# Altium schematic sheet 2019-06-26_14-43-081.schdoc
size 394 x 127 mm; SheetNumber: 1; SheetTotal: 1
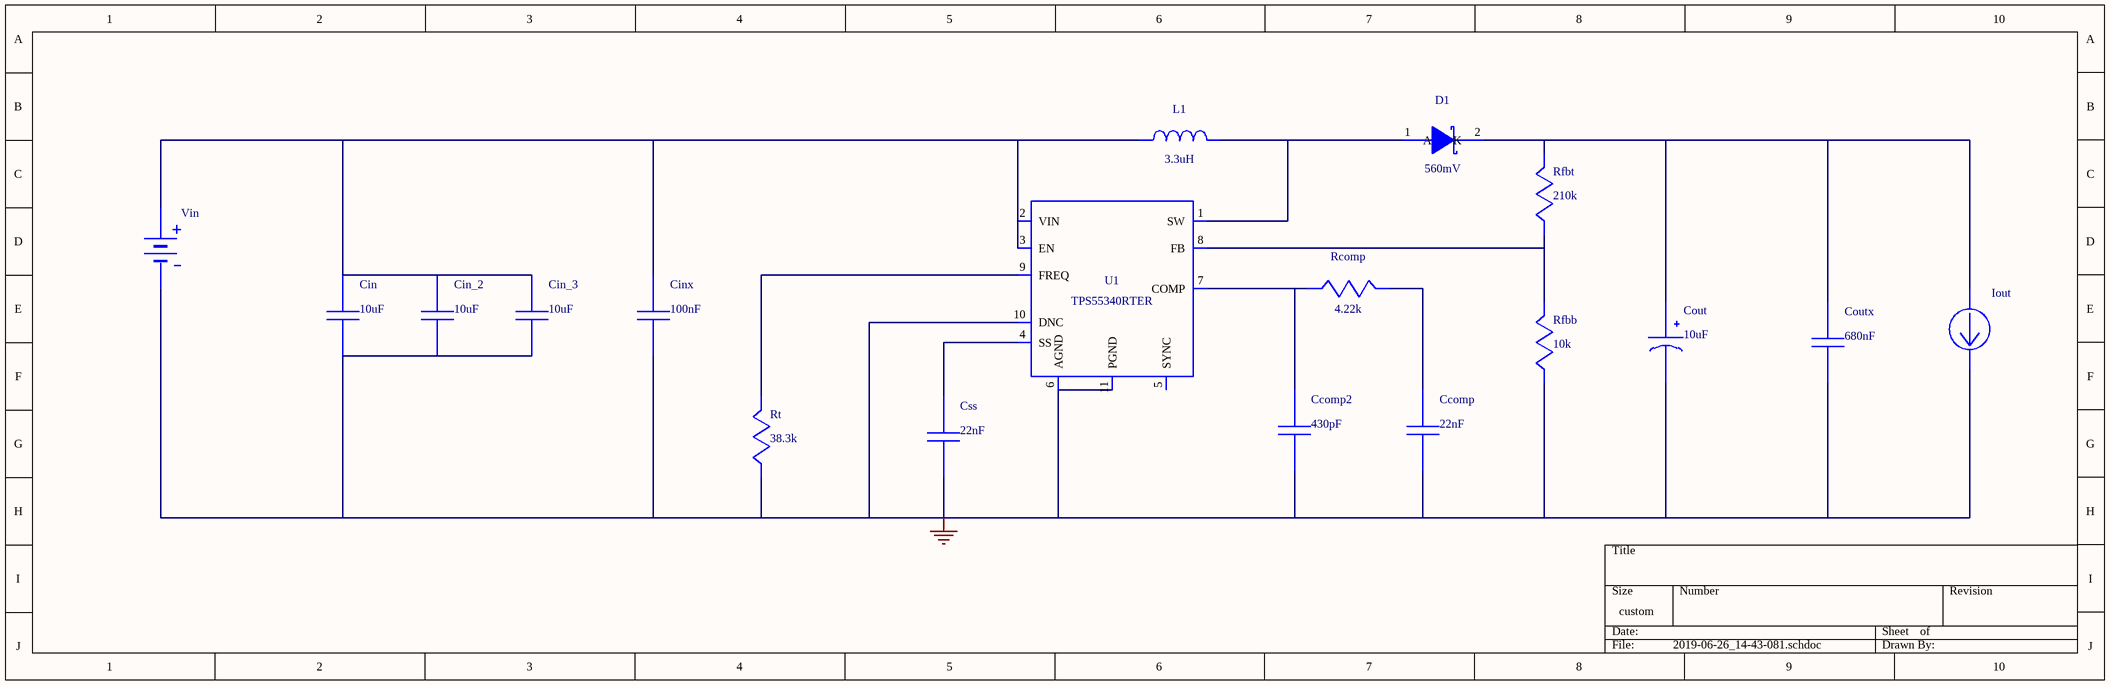
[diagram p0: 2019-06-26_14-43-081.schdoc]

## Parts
Ccomp  value 22nF  (hidden comment: GCM21B5C1H223JA16L)
Ccomp2  value 430pF  (hidden comment: GRM1555C1H431GA01D)
Cin  value 10uF  (hidden comment: GRM31CR61C106KA88L)
Cin_2  value 10uF  (hidden comment: GRM31CR61C106KA88L)
Cin_3  value 10uF  (hidden comment: GRM31CR61C106KA88L)
Cinx  value 100nF  (hidden comment: GRM155R71C104KA88D)
Cout  value 10uF  (hidden comment: 50SVPF10M)
Coutx  value 680nF  (hidden comment: GRM31MR72A684KA35L)
Css  value 22nF  (hidden comment: GRM033R60J223KE01D)
D1  value 560mV  (hidden comment: PDS760-13)
Iout  WB_CURRENT_LOAD  (value not drawn)
L1  value 3.3uH  (hidden comment: XAL5030-332MEB)
Rcomp  value 4.22k  (hidden comment: CRCW04024K22FKED)
Rfbb  value 10k  (hidden comment: RC0201FR-0710KL)
Rfbt  value 210k  (hidden comment: CRCW0402210KFKED)
Rt  value 38.3k  (hidden comment: CRCW040238K3FKED)
U1  TPS55340RTER
Vin  WB_BATTERY  (value not drawn)

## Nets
0: Ccomp.2 Ccomp2.1 Cin.2 Cin_2.2 Cin_3.2 Cinx.2 Cout.2(-) Coutx.2 Css.2 Iout.2(-) Rfbb.2 Rt.2 U1.6(AGND) U1.10(DNC) U1.11(PGND) U1.12(PGND) U1.13(PGND) U1.14(DNC) U1.17(ETPAD) Vin.2(-)
NetCcomp2_2: Ccomp2.2 Rcomp.2 U1.7(COMP)
NetCcomp_1: Ccomp.1 Rcomp.1
NetCin_1: Cin.1 Cin_2.1 Cin_3.1 Cinx.1 L1.2 U1.2(VIN) U1.3(EN) Vin.1(+)
NetCout_1: Cout.1(+) Coutx.1 D1.2(K) Iout.1(+) Rfbt.1
NetCss_1: Css.1 U1.4(SS)
NetD1_1: D1.1(A) D1.3(A) L1.1 U1.1(SW) U1.15(SW) U1.16(SW)
NetRfbb_1: Rfbb.1 Rfbt.2 U1.8(FB)
NetRt_1: Rt.1 U1.9(FREQ)

Not connected (* = marked no-connect by the designer): U1 5(SYNC)

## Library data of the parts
Ccomp = GCM21B5C1H223JA16L: GCM21B5C1H223JA1; Manufacturer Name: MuRata
Ccomp2 = GRM1555C1H431GA01D: GRM1555C1H431GA0; Manufacturer Name: MuRata
Cin Cin_2 Cin_3 = GRM31CR61C106KA88L: GRM31CR61C106KA8; Manufacturer Name: MuRata
Cinx = GRM155R71C104KA88D: GRM155R71C104KA8; Manufacturer Name: MuRata
Cout = 50SVPF10M: Manufacturer Name: Panasonic
Coutx = GRM31MR72A684KA35L: GRM31MR72A684KA3; Manufacturer Name: MuRata
Css = GRM033R60J223KE01D: GRM033R60J223KE0; Manufacturer Name: MuRata
D1 = PDS760-13: Manufacturer Name: Diodes Inc.
L1 = XAL5030-332MEB: Manufacturer Name: Coilcraft
Rcomp = CRCW04024K22FKED: Manufacturer Name: Vishay-Dale
Rfbb = RC0201FR-0710KL: Manufacturer Name: Yageo
Rfbt = CRCW0402210KFKED: Manufacturer Name: Vishay-Dale
Rt = CRCW040238K3FKED: Manufacturer Name: Vishay-Dale
U1 = TPS55340RTER: Manufacturer Name: Texas Instruments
